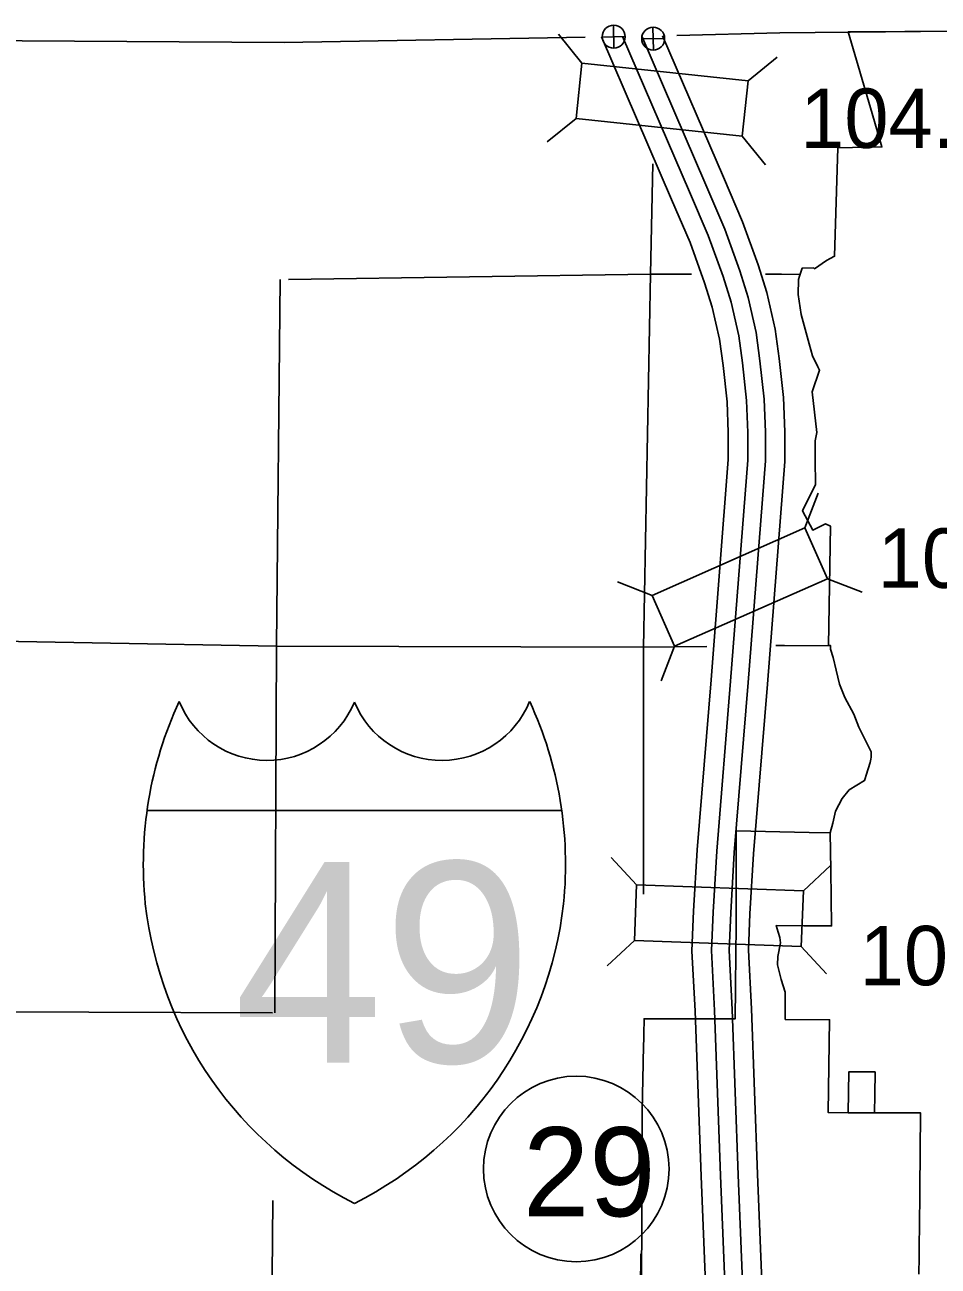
# Model space of a CAD drawing. Extents: x 77230 to 630905, y 790554 to 1662844.
# Drawn here: x 172961 to 185953, y 1620575 to 1638230 of the extents above; entities that cross this region are included whole.
import ezdxf

# ---------------------------------------------------------------- set-up
doc = ezdxf.new("R2010")
doc.units = 0
for name, color, linetype in [('Level 12', 7, 'Continuous'), ('Level 14', 7, 'Continuous'), ('Level 16', 7, 'Continuous'), ('Level 19', 7, 'Continuous'), ('Level 29', 7, 'Continuous'), ('Level 32', 7, 'Continuous'), ('Level 33', 7, 'Continuous'), ('Level 34', 7, 'Continuous'), ('Level 36', 7, 'Continuous')]:
    doc.layers.add(name, color=color, linetype=linetype)

msp = doc.modelspace()

# ---------------------------------------------------------------- linework, layer by layer
at = {"layer": 'Level 12'}
for points in [[(184996, 1627788), (184999, 1627813), (185000, 1627854), (184997, 1627889), (184822, 1628239), (184751, 1628424), (184627, 1628661), (184549, 1628854), (184502, 1629051), (184458, 1629230), (184420, 1629349), (184421, 1629401), (184393, 1629402), (184419, 1631102), (184351, 1631135), (184168, 1631045), (184023, 1631316), (184206, 1631690), (184205, 1632045), (184204, 1632314), (184225, 1632434), (184162, 1633011), (184266, 1633317), (184241, 1633367), (184165, 1633522), (184118, 1633691), (184003, 1634110), (183962, 1634397), (183966, 1634607), (183978, 1634654), (184017, 1634767), (184177, 1634776), (184193, 1634760), (184364, 1634877), (184416, 1634906), (184478, 1634939), (184526, 1636480), (185153, 1636493), (185013, 1636968), (184671, 1638130), (187087, 1638146)], [(185679, 1620461), (185684, 1620707), (185685, 1621316), (185692, 1621449), (185692, 1621666), (185703, 1622749), (185703, 1622754), (185578, 1622754), (185047, 1622756), (185051, 1623012), (185056, 1623337), (184681, 1623338), (184672, 1622757), (184672, 1622757), (184390, 1622758), (184409, 1624080), (183778, 1624085), (183776, 1624471), (183719, 1624650), (183680, 1624804), (183667, 1624859), (183670, 1624979), (183711, 1625173), (183702, 1625248), (183678, 1625327), (183650, 1625421), (184043, 1625417), (184066, 1625417), (184417, 1625413), (184436, 1625413), (184428, 1626214), (184418, 1626740), (184452, 1626877), (184492, 1627044), (184587, 1627226), (184688, 1627348), (184903, 1627482), (184912, 1627510), (184927, 1627557), (184984, 1627738), (184996, 1627788)], [(181731, 1620161), (181735, 1621439), (181741, 1622765), (181747, 1623015), (181751, 1623228), (181756, 1623461), (181758, 1623541), (181760, 1623642), (181765, 1623874), (181770, 1624094), (182466, 1624094), (182960, 1624093), (183066, 1624093), (183070, 1624535), (183070, 1624573), (183077, 1625424), (183077, 1625434), (183078, 1625438), (183079, 1626561), (183079, 1626766), (184116, 1626743), (184418, 1626740), (184428, 1626214), (184436, 1625413), (184417, 1625413), (184066, 1625417), (184043, 1625417), (183650, 1625421), (183678, 1625327), (183702, 1625248), (183711, 1625173), (183670, 1624979), (183667, 1624859), (183680, 1624804), (183719, 1624650), (183776, 1624471), (183778, 1624085), (184409, 1624080), (184390, 1622758), (184672, 1622757), (184880, 1622757), (185047, 1622756), (185578, 1622754), (185703, 1622754), (185703, 1622749), (185692, 1621666), (185692, 1621449), (185685, 1621316), (185684, 1620707), (185679, 1620461)]]:
    msp.add_lwpolyline(points, dxfattribs=at)
at = {"layer": 'Level 14'}
for points in [[(182235, 1638079), (183699, 1638115)], [(183699, 1638115), (187206, 1638149), (192449, 1638139), (197792, 1638203), (203774, 1638211), (209041, 1638230), (212495, 1638216)], [(153234, 1637714), (155742, 1637753), (160979, 1637848), (166173, 1637923), (171425, 1638011), (176649, 1637980), (180931, 1638054)]]:
    msp.add_lwpolyline(points, dxfattribs=at)
at = {"layer": 'Level 16'}
for points in [[(181895, 1636254), (181862, 1634686), (181761, 1629374), (181759, 1625865)], [(176518, 1624179), (176540, 1629401), (176594, 1634608)], [(176709, 1634610), (181862, 1634686), (182442, 1634685)], [(183498, 1634684), (183723, 1634684)], [(183723, 1634684), (183988, 1634681)], [(182661, 1629390), (181755, 1629380), (176540, 1629393), (171294, 1629490), (166079, 1629485)], [(183765, 1629402), (183645, 1629401)], [(183765, 1629402), (184421, 1629398)], [(165997, 1624200), (171252, 1624197), (176482, 1624179)], [(176463, 1618850), (176490, 1621511)], [(181725, 1620751), (181706, 1618783)]]:
    msp.add_lwpolyline(points, dxfattribs=at)
at = {"layer": 'Level 19'}
for p, q in [((180886, 1637685), (180554, 1638096)), ((183249, 1637436), (183660, 1637768)), ((180803, 1636898), (180393, 1636566)), ((183166, 1636648), (183498, 1636238)), ((184056, 1631075), (184247, 1631568)), ((184377, 1630351), (184869, 1630160)), ((181883, 1630115), (181391, 1630306)), ((182203, 1629391), (182013, 1628898)), ((181660, 1625999), (181301, 1626385)), ((184035, 1625912), (184421, 1626271)), ((181631, 1625207), (181245, 1624848)), ((184006, 1625120), (184365, 1624734))]:
    msp.add_line(p, q, dxfattribs=at)
for points in [[(180803, 1636898), (183166, 1636648), (183249, 1637436), (180886, 1637685)], [(182203, 1629391), (184377, 1630351), (184056, 1631075), (181883, 1630115)], [(181631, 1625207), (184006, 1625120), (184035, 1625912), (181660, 1625999)]]:
    msp.add_lwpolyline(points, close=True, dxfattribs=at)
at = {"layer": 'Level 29'}
for points in [[(183927, 1615188), (183459, 1615778), (183211, 1616174), (182974, 1616713), (182853, 1617142), (182772, 1617493), (182738, 1617817), (182708, 1618685), (182579, 1621853), (182495, 1624200), (182449, 1625062), (182472, 1625625), (182526, 1626497), (182724, 1628916), (182966, 1632050), (182966, 1632430), (182951, 1632869), (182892, 1633386), (182841, 1633759), (182740, 1634214), (182631, 1634561), (182424, 1635132), (182161, 1635747), (181163, 1638058)], [(184140, 1615366), (183686, 1615938), (183457, 1616304), (183236, 1616807), (183122, 1617211), (183046, 1617539), (183016, 1617836), (182985, 1618695), (182856, 1621864), (182773, 1624212), (182727, 1625063), (182750, 1625611), (182803, 1626478), (183000, 1628894), (183243, 1632040), (183243, 1632434), (183228, 1632889), (183168, 1633421), (183115, 1633808), (183008, 1634285), (182895, 1634649), (182682, 1635234), (182417, 1635857), (181464, 1638064)], [(184333, 1615526), (183891, 1616083), (183680, 1616422), (183473, 1616892), (183365, 1617274), (183294, 1617580), (183266, 1617853), (183236, 1618705), (183107, 1621873), (183023, 1624223), (182978, 1625065), (183001, 1625598), (183053, 1626460), (183251, 1628874), (183494, 1632030), (183494, 1632438), (183479, 1632908), (183417, 1633452), (183362, 1633852), (183251, 1634350), (183133, 1634730), (182916, 1635326), (182647, 1635956), (181735, 1638068)], [(184544, 1615702), (184116, 1616242), (183923, 1616550), (183732, 1616985), (183631, 1617342), (183565, 1617625), (183540, 1617872), (183510, 1618715), (183381, 1621884), (183297, 1624235), (183253, 1625067), (183275, 1625584), (183327, 1626440), (183524, 1628853), (183769, 1632019), (183769, 1632443), (183753, 1632928), (183689, 1633486), (183632, 1633900), (183516, 1634421), (183393, 1634818), (183171, 1635427), (182899, 1636064), (182031, 1638074)]]:
    msp.add_lwpolyline(points, dxfattribs=at)
at = {"layer": 'Level 33'}
msp.add_circle((180805, 1621957), 1320, dxfattribs=at)
at = {"layer": 'Level 34'}
for p, q in [((181340, 1637898), (181333, 1638224)), ((181902, 1637871), (181895, 1638197)), ((181174, 1638057), (181499, 1638065)), ((181736, 1638030), (182061, 1638038))]:
    msp.add_line(p, q, dxfattribs=at)
for centre in [(181337, 1638061), (181899, 1638034)]:
    msp.add_circle(centre, 163, dxfattribs=at)
at = {"layer": 'Level 36'}
msp.add_line((174700, 1627056), (180598, 1627056), dxfattribs=at)
for centre, radius, start, end in [((180181, 1626287), 5535, 155.2204, 185.7928), ((176405, 1629116), 1348, 202.1459, 337.3414), ((178893, 1629116), 1348, 202.6586, 337.8541), ((175117, 1626287), 5535, 354.2072, 24.7796), ((180080, 1626334), 5439, 186.3923, 243.4571), ((175218, 1626334), 5439, 296.5429, 353.6077)]:
    msp.add_arc(centre, radius, start, end, dxfattribs=at)

# ---------------------------------------------------------------- texts
at = {"layer": 'Level 32'}
for s, p in [('104.97(O.P.)', (183990, 1636479)), ('103.55(O.P.)', (185092, 1630223)), ('102.69(O.P.)', (184836, 1624570))]:
    msp.add_text(s, height=844.8, dxfattribs=at).set_placement(p)
at = {"layer": 'Level 33'}
msp.add_text('29', height=1267.2, dxfattribs=at).set_placement((180047, 1621284))
at = {"layer": 'Level 36'}
msp.add_text('49', height=2851.2, dxfattribs=at).set_placement((175935, 1623471))

doc.saveas('drawing.dxf')
